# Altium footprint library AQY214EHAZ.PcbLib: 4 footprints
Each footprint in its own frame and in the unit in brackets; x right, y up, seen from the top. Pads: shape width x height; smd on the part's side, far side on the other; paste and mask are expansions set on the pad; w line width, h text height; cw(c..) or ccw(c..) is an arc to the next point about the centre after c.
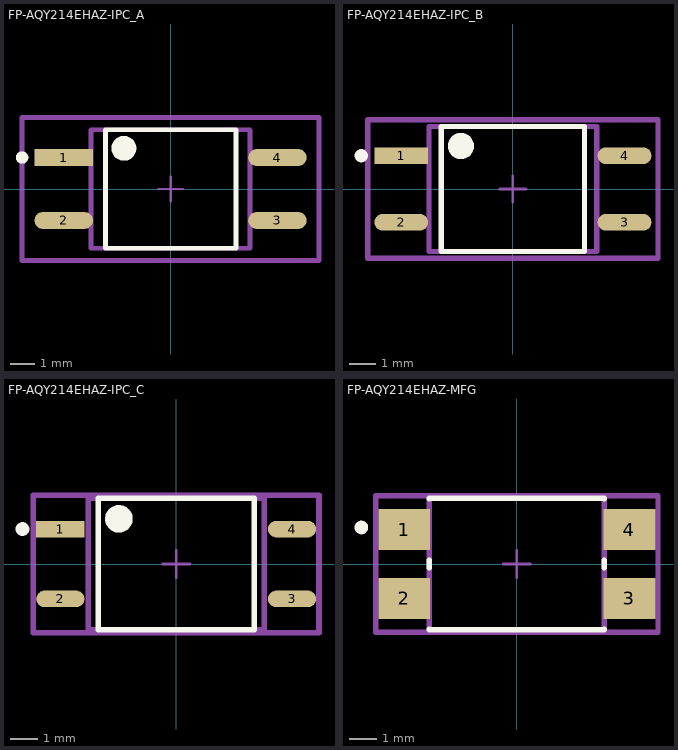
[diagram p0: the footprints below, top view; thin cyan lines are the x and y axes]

## FP-AQY214EHAZ-IPC_A [mil]
pads (4):
  rect 92.7x26.86 smd paste+0 mask+0: 1(-169.69,50)
  rrect100% 92.7x26.86 smd paste+0 mask+0: 2(-169.69,-50) 3(169.69,-50) 4(169.69,50)
Top Overlay:
  circle w19.68: c-74.13,64.57 r9.84
  circle w9.84: c-235.73,50 r4.92
  lines w7.87: -103.65,-94.09 103.65,-94.09 103.65,94.09 -103.65,94.09 -103.65,-94.09
Top Assembly:
  lines w7.87: -235.73,-113.78 235.73,-113.78 235.73,113.78 -235.73,113.78 -235.73,-113.78
  text ".Designator" at 0,7.39 h39.37
Top 3D Body:
  lines w7.87: -125.98,-94.09 125.98,-94.09 125.98,94.09 -125.98,94.09 -125.98,-94.09
Top Courtyard:
  lines w7.87: -235.73,-113.78 235.73,-113.78 235.73,113.78 -235.73,113.78 -235.73,-113.78
Top Component Center:
  lines w3.94: -19.68,0 19.68,0 ; 0,-19.68 0,19.68
3D body "Relay_Panasonic_AQY214EHAZ_eec.STEP": height 10, standoff 0, extent -235.73,-113.78 235.73,113.78

## FP-AQY214EHAZ-IPC_B [mil]
pads (4):
  rect 80.89x25.28 smd paste+0 mask+0: 1(-167.72,50)
  rrect100% 80.89x25.28 smd paste+0 mask+0: 2(-167.72,-50) 3(167.72,-50) 4(167.72,50)
Top Overlay:
  circle w19.68: c-78.06,64.57 r9.84
  circle w9.84: c-227.85,50 r4.92
  lines w7.87: -107.59,-94.09 107.59,-94.09 107.59,94.09 -107.59,94.09 -107.59,-94.09
Top Assembly:
  lines w7.87: -218.01,-103.94 218.01,-103.94 218.01,103.94 -218.01,103.94 -218.01,-103.94
  text ".Designator" at 0,7.39 h39.37
Top 3D Body:
  lines w7.87: -125.98,-94.09 125.98,-94.09 125.98,94.09 -125.98,94.09 -125.98,-94.09
Top Courtyard:
  lines w7.87: -218.01,-103.94 218.01,-103.94 218.01,103.94 -218.01,103.94 -218.01,-103.94
Top Component Center:
  lines w3.94: -19.68,0 19.68,0 ; 0,-19.68 0,19.68
3D body "Relay_Panasonic_AQY214EHAZ_eec.STEP": height 10, standoff 0, extent -218.01,-103.94 218.01,103.94

## FP-AQY214EHAZ-IPC_C [mil]
pads (4):
  rect 69.08x23.71 smd paste+0 mask+0: 1(-165.75,50)
  rrect100% 69.08x23.71 smd paste+0 mask+0: 2(-165.75,-50) 3(165.75,-50) 4(165.75,50)
Top Overlay:
  circle w19.68: c-82,64.57 r9.84
  circle w9.84: c-219.98,50 r4.92
  lines w7.87: -111.53,-94.09 111.53,-94.09 111.53,94.09 -111.53,94.09 -111.53,-94.09
Top Assembly:
  lines w7.87: -204.23,-98.03 204.23,-98.03 204.23,98.03 -204.23,98.03 -204.23,-98.03
  text ".Designator" at 0,7.39 h39.37
Top 3D Body:
  lines w7.87: -125.98,-94.09 125.98,-94.09 125.98,94.09 -125.98,94.09 -125.98,-94.09
Top Courtyard:
  lines w7.87: -204.23,-98.03 204.23,-98.03 204.23,98.03 -204.23,98.03 -204.23,-98.03
Top Component Center:
  lines w3.94: -19.68,0 19.68,0 ; 0,-19.68 0,19.68
3D body "Relay_Panasonic_AQY214EHAZ_eec.STEP": height 10, standoff 0, extent -204.23,-98.03 204.23,98.03

## FP-AQY214EHAZ-MFG [mm]
pads (4):
  rect 1.9x1.5 smd paste+0 mask+0: 1(-4.15,1.27) 2(-4.15,-1.27) 3(4.15,-1.27) 4(4.15,1.27)
Top Overlay:
  circle w0.25: c-5.725,1.345 r0.125
  lines w0.2: -3.225,-2.395 -3.225,-2.415 3.225,-2.415 3.225,-2.395 ; -3.225,-0.145 -3.225,0.145 ; -3.225,2.395 -3.225,2.415 3.225,2.415 3.225,2.395 ; 3.225,-0.145 3.225,0.145
Top Assembly:
  lines w0.2: -5.2,-2.515 5.2,-2.515 5.2,2.515 -5.2,2.515 -5.2,-2.515
  text ".Designator" at 0,0.188 h1
Top 3D Body:
  lines w0.2: -3.225,-2.415 3.225,-2.415 3.225,2.415 -3.225,2.415 -3.225,-2.415
Top Courtyard:
  lines w0.2: -5.2,-2.515 5.2,-2.515 5.2,2.515 -5.2,2.515 -5.2,-2.515
Top Component Center:
  lines w0.1: -0.5,0 0.5,0 ; 0,-0.5 0,0.5
3D body "Relay_Panasonic_AQY214EHAZ_eec.STEP": height 0.25, standoff 0, extent -5.2,-2.515 5.2,2.515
